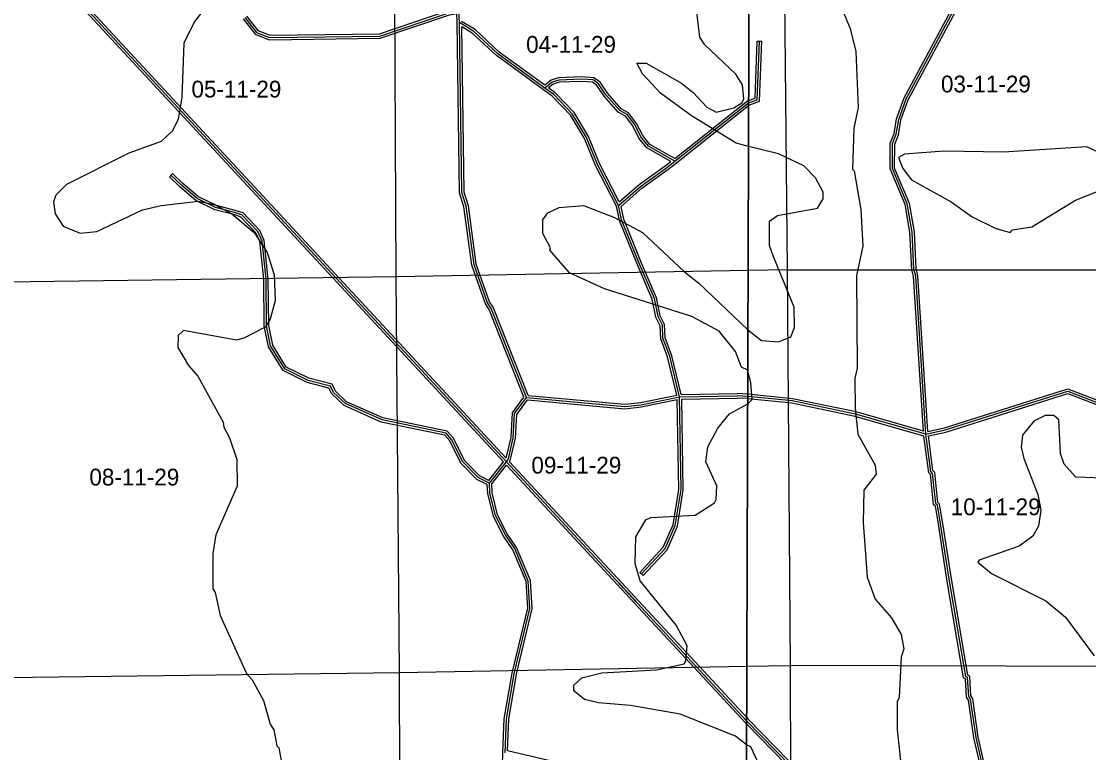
# Model space of a CAD drawing. Extents: x 457167 to 656239, y 1787309 to 1969297.
# Drawn here: x 527283 to 541585, y 1896458 to 1906256 of the extents above; entities that cross this region are included whole.
import ezdxf

# ---------------------------------------------------------------- set-up
doc = ezdxf.new("R2010")
doc.units = 0
for name, color, linetype in [('Level 1', 7, 'Continuous'), ('Level 2', 7, 'Continuous'), ('Level 31', 7, 'Continuous'), ('Level 32', 7, 'Continuous'), ('Level 34', 7, 'Continuous'), ('Level 63', 7, 'Continuous'), ('Level 7', 7, 'Continuous')]:
    doc.layers.add(name, color=color, linetype=linetype)

msp = doc.modelspace()

# ---------------------------------------------------------------- linework, layer by layer
at = {"layer": 'Level 1'}
for p, q in [((537491.16, 1908193.626), (537546.665, 1902924.331)), ((532306.15, 1902834.307), (532281.084, 1907962.091)), ((532306.15, 1902834.307), (527074.045, 1902759.436)), ((537021.377, 1902915.308), (532306.15, 1902834.307)), ((532349.253, 1897530.544), (532306.15, 1902834.307)), ((537546.665, 1902924.331), (537021.377, 1902915.308)), ((537546.665, 1902924.331), (542788.198, 1902925.546)), ((537546.665, 1902924.331), (537585.575, 1897625.288)), ((532349.253, 1897530.544), (537004.347, 1897614.771)), ((537004.347, 1897614.771), (537585.575, 1897625.288)), ((537585.575, 1897625.288), (537599.773, 1892290.637)), ((542838.747, 1897608.236), (537585.575, 1897625.288)), ((527079.285, 1897466.086), (532349.253, 1897530.544)), ((532368.304, 1892221.06), (532349.253, 1897530.544))]:
    msp.add_line(p, q, dxfattribs=at)
at = {"layer": 'Level 31'}
for p, q in [((533783.107, 1900354.301), (527053.695, 1907611.555)), ((533152.758, 1906238.376), (533145.019, 1906396.589)), ((536101.815, 1901225.282), (536875.394, 1901239.147)), ((533554.83, 1900067.776), (533783.107, 1900354.301))]:
    msp.add_line(p, q, dxfattribs=at)
for points in [[(539403.889, 1900723.442), (539267.811, 1902841.381), (539243.303, 1902933.097), (539219.447, 1903433.186), (539153.87, 1903808.675), (538955.089, 1904284.226), (538955.825, 1904617.687), (539006.131, 1904742.621), (539040.143, 1904942.521), (539140.832, 1905217.482), (539836.34, 1906516.053), (539828.149, 1906641.173), (539753.599, 1906791.23), (539205.078, 1907443.159), (538923.034, 1907918.973), (538840.41, 1908227.608), (538841.86, 1908786.165), (538892.32, 1908961.283), (538909.852, 1909277.964)], [(530277.025, 1906307.319), (530434.654, 1906106.777), (530609.585, 1906039.272), (532085.312, 1906058.661), (533011.74, 1906371.94), (533145.019, 1906396.589)], [(534051.109, 1901216.35), (533580.38, 1902410.301), (533530.714, 1902485.377), (533349.277, 1902994.72), (533243.784, 1903778.729), (533185.897, 1903962.199), (533152.758, 1906238.376)], [(534296.83, 1905361.84), (533668.266, 1905819.563), (533344.057, 1906120.646), (533152.758, 1906238.376)], [(537028.605, 1905164.967), (537143.114, 1905206.031), (537174.557, 1905989.588)], [(536041.144, 1904381.93), (535685.421, 1904582.364), (535583.468, 1904708.881), (535501.983, 1904873.151), (535400.059, 1905008.396), (535300.73, 1905061.813), (535117.03, 1905270.782), (535018.325, 1905417.656), (534945.063, 1905470.624), (534790.278, 1905480.222), (534486.015, 1905469.584), (534395.32, 1905440.791), (534296.83, 1905361.84)], [(535286.085, 1903787.642), (535004.943, 1904338.759), (534856.065, 1904697.802), (534665.41, 1905015.527), (534416.392, 1905274.898), (534296.83, 1905361.84)], [(536041.144, 1904381.93), (537028.537, 1905164.943), (537028.605, 1905164.967)], [(535286.085, 1903787.642), (535578.764, 1904044.877), (535929.91, 1904293.925), (536041.144, 1904381.93)], [(531425.795, 1901368.011), (531125.288, 1901444.664), (530812.653, 1901601.361), (530623.565, 1901907.101), (530568.842, 1902177.113), (530561.738, 1902801.518), (530507.831, 1903311.899), (530452.624, 1903437.908), (530236.884, 1903661.921), (530140.349, 1903694.613), (529886.24, 1903760.208), (529638.046, 1903881.423), (529427.885, 1904061.056), (529287.821, 1904193.54)], [(536101.815, 1901225.282), (535970.677, 1901767.541), (535879.58, 1902009.661), (535872.201, 1902184.963), (535814.083, 1902301.881), (535764.954, 1902543.866), (535566.791, 1903003.069), (535327.105, 1903595.867), (535286.085, 1903787.642)], [(533554.83, 1900067.776), (533405.01, 1900143.183), (533197.451, 1900352.605), (533048.698, 1900653.106), (532973.944, 1900736.995), (532115.786, 1900915.136), (531624.987, 1901133.516), (531467.163, 1901284.233), (531425.795, 1901368.011)], [(539403.889, 1900723.442), (539662.555, 1900781.175), (541306.314, 1901301.874), (542413.95, 1900873.718), (542755.475, 1900789.396), (543239.054, 1900788.284), (543805.714, 1900820.016), (544706.73, 1901026.027), (545795.278, 1901112.589)], [(533817.705, 1900433.462), (533874.142, 1900675.101), (533891.746, 1901000.142), (534051.109, 1901216.35)], [(534051.109, 1901216.35), (535367.915, 1901094.574), (535584.508, 1901118.96), (536101.815, 1901225.282)], [(535592.715, 1898851.237), (535910.82, 1899192.031), (536045.358, 1899499.966), (536122.275, 1899983.001), (536101.815, 1901225.282)], [(537015.964, 1901230.324), (537015.893, 1901230.331), (536875.394, 1901239.147)], [(539403.889, 1900723.442), (538462.692, 1900992.61), (537612.78, 1901169.87), (537015.964, 1901230.324)], [(540175.46, 1896228.182), (540076.653, 1896661.593), (540003.205, 1897170.562), (539978.215, 1897212.096), (539962.147, 1897462.334), (539937.08, 1897479.141), (539715.726, 1898780.231), (539600.733, 1899522.428), (539559.87, 1899772.746), (539534.829, 1899797.552), (539494.438, 1900198.053), (539469.399, 1900222.86), (539403.889, 1900723.442)], [(533783.107, 1900354.301), (533806.095, 1900383.681), (533817.705, 1900433.462)], [(533783.107, 1900354.301), (537001.932, 1896884.447), (537002, 1896884.377)], [(533766.432, 1896457.162), (533784.77, 1896907.296), (533887.255, 1897515.7), (534098.717, 1898389.935), (534075.124, 1898756.931), (533893.413, 1899190.997), (533769.065, 1899375.049), (533636.699, 1899634.038), (533562.656, 1899934.292), (533554.83, 1900067.776)], [(537002, 1896884.377), (538796.79, 1895046.313), (539676.085, 1894559.165)]]:
    msp.add_lwpolyline(points, dxfattribs=at)
at = {"layer": 'Level 32'}
for p, q in [((533743.569, 1900352.818), (527031.697, 1907591.156)), ((533779.608, 1900402.198), (527075.695, 1907631.953)), ((533122.769, 1906237.425), (533116.731, 1906360.846)), ((537144.581, 1905990.791), (537204.534, 1905988.385)), ((536059.785, 1904358.423), (537028.483, 1905126.611)), ((529267.205, 1904171.745), (529308.437, 1904215.335)), ((536125.324, 1901255.708), (536876.067, 1901269.164)), ((537016.06, 1901260.381), (536876.066, 1901269.164)), ((536132.306, 1901195.823), (536874.723, 1901209.13)), ((533779.608, 1900402.198), (533788.489, 1900440.276)), ((533546.552, 1900105.529), (533743.569, 1900352.818)), ((533585.453, 1900058.065), (533784.836, 1900308.325)), ((533822.494, 1900355.954), (537002.141, 1896928.335)), ((535570.785, 1898871.708), (535614.646, 1898830.766)), ((536069.689, 1895951.319), (533797.419, 1896480.746))]:
    msp.add_line(p, q, dxfattribs=at)
for points in [[(539371.222, 1900763.987), (539238.063, 1902836.5), (539213.49, 1902928.457), (539189.57, 1903429.877), (539124.895, 1903800.204), (538925.075, 1904278.24), (538925.838, 1904623.533), (538977.097, 1904750.835), (539011.028, 1904950.258), (539113.388, 1905229.784), (539805.843, 1906522.655), (539798.605, 1906633.211), (539728.33, 1906774.664), (539180.53, 1907425.735), (538895.121, 1907907.227), (538810.399, 1908223.7), (538811.87, 1908790.439), (538862.552, 1908966.329), (538878.72, 1909258.346)], [(539431.58, 1900760.361), (539297.56, 1902846.262), (539273.115, 1902937.736), (539249.324, 1903436.493), (539182.845, 1903817.146), (538985.103, 1904290.212), (538985.813, 1904611.841), (539035.165, 1904734.409), (539069.258, 1904934.782), (539168.276, 1905205.181), (539866.836, 1906509.452), (539857.693, 1906649.135), (539778.867, 1906807.796), (539229.625, 1907460.583), (538950.946, 1907930.72), (538870.42, 1908231.516), (538871.85, 1908781.89), (538922.087, 1908956.236), (538938.222, 1909247.672)], [(530300.612, 1906325.858), (530453.145, 1906131.798), (530614.982, 1906069.346), (532080.185, 1906088.596), (533004.169, 1906401.049), (533123.955, 1906423.201)], [(530253.438, 1906288.78), (530416.162, 1906081.756), (530604.188, 1906009.198), (532090.439, 1906028.725), (533019.313, 1906342.831), (533116.731, 1906360.846)], [(534017.111, 1901220.787), (533553.624, 1902396.372), (533503.679, 1902471.87), (533319.963, 1902987.61), (533214.395, 1903772.166), (533155.964, 1903957.366), (533122.769, 1906237.425)], [(534295.956, 1905399.588), (533687.371, 1905842.763), (533362.303, 1906144.645), (533181.951, 1906255.636)], [(534279.17, 1905337.588), (533649.161, 1905796.363), (533325.811, 1906096.648), (533183.552, 1906184.199)], [(534072.25, 1901244.522), (533607.136, 1902424.231), (533557.749, 1902498.885), (533378.59, 1903001.831), (533273.171, 1903785.291), (533215.83, 1903967.032), (533183.552, 1906184.198)], [(537028.483, 1905126.611), (537043.31, 1905138.37), (537172.279, 1905184.618), (537204.534, 1905988.385)], [(537028.708, 1905196.876), (537113.949, 1905227.443), (537144.581, 1905990.791)], [(536038.304, 1904417.965), (535705.166, 1904605.674), (535608.885, 1904725.151), (535527.62, 1904888.98), (535420.06, 1905031.704), (535319.695, 1905085.677), (535140.845, 1905289.13), (535040.24, 1905438.831), (534955.596, 1905500.029), (534790.684, 1905510.256), (534480.857, 1905499.423), (534380.915, 1905467.694), (534295.955, 1905399.588)], [(535987.484, 1904377.729), (535665.676, 1904559.054), (535558.05, 1904692.611), (535476.346, 1904857.322), (535380.058, 1904985.089), (535281.764, 1905037.949), (535093.214, 1905252.435), (534996.41, 1905396.48), (534934.53, 1905441.219), (534789.873, 1905450.189), (534491.173, 1905439.745), (534409.724, 1905413.886), (534346.245, 1905363.001)], [(535257.572, 1903777.516), (534977.683, 1904326.177), (534829.201, 1904684.265), (534641.427, 1904997.19), (534396.595, 1905252.2), (534279.186, 1905337.576)], [(535295.27, 1903835.656), (535032.204, 1904351.341), (534882.93, 1904711.339), (534689.395, 1905033.865), (534436.189, 1905297.596), (534346.245, 1905363.001)], [(536038.304, 1904417.965), (537013.764, 1905191.517), (537028.708, 1905196.876)], [(535295.27, 1903835.656), (535560.133, 1904068.444), (535911.912, 1904317.941), (535987.484, 1904377.729)], [(535319.101, 1903776.719), (535597.395, 1904021.311), (535947.906, 1904269.908), (536059.758, 1904358.401)], [(531405.006, 1901342.352), (531114.738, 1901416.394), (530791.61, 1901578.35), (530595.229, 1901895.884), (530538.876, 1902173.935), (530531.755, 1902799.769), (530478.485, 1903304.121), (530427.295, 1903420.958), (530220.342, 1903635.848), (530131.777, 1903665.841), (529875.803, 1903731.918), (529621.453, 1903856.14), (529407.818, 1904038.742), (529267.205, 1904171.745)], [(531446.585, 1901393.669), (531135.837, 1901472.933), (530833.696, 1901624.371), (530651.902, 1901918.319), (530598.809, 1902180.291), (530591.72, 1902803.268), (530537.178, 1903319.677), (530477.951, 1903454.858), (530253.425, 1903687.993), (530148.921, 1903723.385), (529896.679, 1903788.498), (529654.64, 1903906.706), (529447.951, 1904083.371), (529308.437, 1904215.335)], [(536065.356, 1901248.416), (535941.95, 1901758.7), (535849.808, 1902003.596), (535842.496, 1902177.324), (535785.465, 1902292.054), (535736.173, 1902534.842), (535539.109, 1902991.501), (535298.315, 1903587.041), (535257.572, 1903777.516)], [(536125.324, 1901255.708), (535999.404, 1901776.382), (535909.352, 1902015.726), (535901.907, 1902192.602), (535842.7, 1902311.71), (535793.734, 1902552.89), (535594.475, 1903014.637), (535355.897, 1903604.693), (535319.101, 1903776.718)], [(533525.895, 1900048.754), (533387.149, 1900118.586), (533172.721, 1900334.939), (533023.607, 1900636.17), (532958.14, 1900709.635), (532106.534, 1900886.416), (531608.034, 1901108.222), (531442.61, 1901266.197), (531405.006, 1901342.352)], [(533546.552, 1900105.529), (533422.872, 1900167.78), (533222.182, 1900370.271), (533073.789, 1900670.044), (532989.746, 1900764.355), (532125.038, 1900943.856), (531641.94, 1901158.809), (531491.715, 1901302.269), (531446.585, 1901393.669)], [(539371.221, 1900763.987), (538469.889, 1901021.755), (537617.367, 1901199.56), (537018.345, 1901260.237), (537016.06, 1901260.381)], [(539431.58, 1900760.361), (539654.742, 1900810.171), (541307.3, 1901333.656), (542422.99, 1900902.388), (542759.157, 1900819.389), (543238.249, 1900818.286), (543801.501, 1900849.827), (544702.173, 1901055.761), (545742.53, 1901138.489)], [(539437.195, 1900700.136), (539670.366, 1900752.179), (541305.327, 1901270.091), (542404.911, 1900845.048), (542751.791, 1900759.404), (543239.858, 1900758.281), (543809.926, 1900790.204), (544711.285, 1900996.294), (545797.655, 1901082.682)], [(533788.491, 1900440.286), (533844.329, 1900679.356), (533862.275, 1901010.722), (534017.111, 1901220.787)], [(533846.92, 1900426.639), (533903.956, 1900670.845), (533921.218, 1900989.562), (534065.211, 1901184.916)], [(534065.21, 1901184.916), (535368.216, 1901064.417), (535589.216, 1901089.301), (536072.416, 1901188.611)], [(534072.25, 1901244.523), (535367.615, 1901124.731), (535579.8, 1901148.62), (536065.356, 1901248.416)], [(535570.785, 1898871.708), (535885.385, 1899208.747), (536016.334, 1899508.466), (536092.235, 1899985.13), (536072.416, 1901188.611)], [(535614.646, 1898830.766), (535936.255, 1899175.313), (536074.383, 1899491.466), (536152.315, 1899980.874), (536132.306, 1901195.823)], [(537015.866, 1901200.18), (537013.44, 1901200.426), (536874.724, 1901209.13)], [(539376.7, 1900700.014), (538455.496, 1900963.465), (537608.193, 1901140.18), (537015.866, 1901200.18)], [(540146.665, 1896219.522), (540047.133, 1896656.107), (539974.377, 1897160.285), (539948.744, 1897202.886), (539933.155, 1897445.652), (539909.667, 1897461.401), (539686.113, 1898775.417), (539571.105, 1899517.715), (539531.83, 1899758.292), (539506.061, 1899783.822), (539465.67, 1900184.323), (539440.985, 1900208.779), (539376.7, 1900700.015)], [(540204.256, 1896236.841), (540106.172, 1896667.079), (540032.033, 1897180.841), (540007.686, 1897221.306), (539991.138, 1897479.016), (539964.494, 1897496.881), (539745.34, 1898785.043), (539630.361, 1899527.142), (539587.908, 1899787.198), (539563.597, 1899811.282), (539523.205, 1900211.783), (539497.812, 1900236.941), (539437.195, 1900700.136)], [(533822.494, 1900355.954), (533833.806, 1900370.412), (533846.922, 1900426.648)], [(533784.836, 1900308.325), (536980.198, 1896863.762), (537001.862, 1896841.576)], [(533736.444, 1896458.001), (533754.871, 1896910.411), (533857.846, 1897521.726), (534068.485, 1898392.559), (534045.508, 1898749.987), (533866.889, 1899176.667), (533743.183, 1899359.768), (533608.404, 1899623.481), (533532.868, 1899929.785), (533525.895, 1900048.754)], [(533797.42, 1896480.746), (533814.669, 1896904.181), (533916.662, 1897509.674), (534128.949, 1898387.311), (534104.74, 1898763.876), (533919.937, 1899205.327), (533794.947, 1899390.33), (533664.995, 1899644.596), (533592.444, 1899938.799), (533585.453, 1900058.065)], [(537001.862, 1896841.576), (538778.4, 1895022.204), (539661.545, 1894532.922)], [(537002.141, 1896928.335), (537023.665, 1896905.131), (538815.179, 1895070.421), (539665.508, 1894599.321)], [(534496.094, 1894042.885), (533875.793, 1895135.635), (533766.995, 1895457.841), (533717.258, 1895771.626), (533736.444, 1896458.001)]]:
    msp.add_lwpolyline(points, dxfattribs=at)
at = {"layer": 'Level 63'}
for points in [[(497176.54, 1878534.741), (536942.563, 1878385.707), (537088.612, 1923840.983), (497371.386, 1923990.389), (497176.54, 1878534.741)], [(536942.563, 1878385.707), (576708.29, 1878279.4), (576805.546, 1923734.416), (537088.612, 1923840.983), (536942.563, 1878385.707)]]:
    msp.add_lwpolyline(points, dxfattribs=at)
at = {"layer": 'Level 7'}
for points in [[(538142.63, 1906753.116), (538390.794, 1906160.446), (538464.84, 1905851.74), (538495.773, 1905101.372), (538436.536, 1904826.465), (538418.105, 1904276.331), (538443.045, 1904251.231), (538533.075, 1903734.081), (538556.524, 1903242.169), (538471.879, 1902850.618), (538484.569, 1901608.469), (538450.8, 1901475.186), (538457.867, 1901075.006), (538490.103, 1900724.788), (538722.174, 1900307.211), (538738.456, 1900190.439), (538571.046, 1899974.251), (538561.303, 1899540.791), (538617.306, 1898806.995), (538724.763, 1898514.869), (538940.69, 1898264.086), (539073.357, 1898038.582), (539106.08, 1897846.748), (539072.411, 1897738.475), (539045.64, 1897196.671), (539020.46, 1897138.42), (539019.256, 1896763.281), (539067.835, 1896312.951)], [(529755.252, 1906446.602), (529604.573, 1906255.356), (529461.915, 1905964.007), (529434.586, 1905238.84), (529383.62, 1904947.232), (529308.101, 1904789.068), (529157.591, 1904647.842), (528723.575, 1904490.853), (527888.606, 1904068.382), (527746.436, 1903927.117), (527712.797, 1903835.525), (527737.28, 1903677.031), (527845.135, 1903509.979), (528069.92, 1903417.56), (528295.065, 1903441.843), (528904.561, 1903731.657), (529154.845, 1903789.192), (529655.194, 1903845.95), (529880.109, 1903795.211), (530104.825, 1903677.781), (530404.125, 1903426.71), (530578.333, 1903159.396), (530669.09, 1902858.99), (530684.645, 1902517.161), (530617.139, 1902267.275), (530550.129, 1902159.131), (530266.206, 1902009.984), (530166.105, 1901985.272), (529457.909, 1902112.606), (529382.649, 1902046.144), (529382.161, 1901887.751), (529523.098, 1901645.576), (529647.683, 1901503.435), (529987.51, 1900885.464), (529995.62, 1900818.743), (530070.185, 1900676.791), (530169.281, 1900384.695), (530176.467, 1900026.196), (529890.943, 1899376.877), (529848.486, 1899126.921), (529846.944, 1898651.74), (529880.125, 1898601.629), (529945.842, 1898292.952), (530301.821, 1897516.529), (530376.585, 1897432.938), (530525.761, 1897157.343), (530616.409, 1896840.266), (530666.2, 1896765.076), (530707.195, 1896548.201), (530732.106, 1896523.131), (530781.281, 1896256.205)], [(537026.729, 1904580.938), (536860.32, 1904623.13), (536261.282, 1904991.851), (535845.439, 1905293.273), (535604.51, 1905552.486), (535529.936, 1905694.458), (535654.979, 1905694.04), (536129.302, 1905425.77), (536287.267, 1905300.199), (536470.084, 1905107.876), (536594.897, 1905040.796), (536828.511, 1905098.401), (536937.072, 1905164.724), (536962.252, 1905214.686), (536946.198, 1905406.45), (536854.955, 1905548.461), (536439.38, 1905941.616), (536373.017, 1906041.877), (536324.3, 1906450.526)], [(537018.829, 1902121.898), (537019.043, 1902121.693), (537201.989, 1901979.391), (537427.003, 1901961.964), (537593.925, 1902028.138), (537644.364, 1902153.011), (537636.91, 1902428.148), (537355.663, 1903112.641), (537306.1, 1903254.523), (537307.145, 1903579.641), (537415.745, 1903654.314), (537949.604, 1903752.643), (538025.024, 1903877.427), (538025.312, 1903969.129), (537925.897, 1904161.192), (537768.031, 1904320.075), (537426.732, 1904479.574), (537026.913, 1904580.891), (537026.729, 1904580.938)], [(537017.086, 1901579.928), (536934.049, 1901621.78), (536851.374, 1901830.444), (536635.505, 1902106.237), (536269.335, 1902299.147), (535095.087, 1902669.741), (534628.935, 1902887.951), (534363.155, 1903188.944), (534371.585, 1903222.255), (534272.17, 1903414.318), (534272.766, 1903597.723), (534339.746, 1903689.196), (534490.028, 1903763.73), (534815.244, 1903787.694), (535231.534, 1903627.966), (535606.015, 1903426.716), (536171.224, 1902899.691), (536362.47, 1902749.019), (537018.829, 1902121.898)], [(537015.64, 1901129.555), (537015.849, 1901129.669), (537074.399, 1901187.831), (537058.445, 1901412.976), (537017.281, 1901579.83), (537017.086, 1901579.928)], [(537000.963, 1896561.512), (536851.517, 1896678.541), (536110.539, 1896972.7), (535443.985, 1897091.534), (535018.966, 1897126.259), (534827.361, 1897168.558), (534686.007, 1897285.729), (534686.236, 1897360.751), (534794.936, 1897460.434), (535061.92, 1897526.269), (535795.653, 1897565.6), (536162.709, 1897647.786), (536187.849, 1897689.367), (536205.175, 1897889.412), (536055.999, 1898164.967), (535574.39, 1898758.415), (535508.445, 1898992.03), (535517.929, 1899350.458), (535652.028, 1899575.116), (535718.819, 1899608.266), (536310.83, 1899639.715), (536569.771, 1899805.592), (536594.911, 1899847.214), (536603.839, 1900030.578), (536454.83, 1900356.184), (536480.488, 1900556.159), (536614.656, 1900805.826), (536773.666, 1900997.043), (537015.64, 1901129.555)], [(541906.097, 1900130.258), (541414.317, 1900148.532), (541256.481, 1900324.084), (541206.919, 1900465.966), (541183.351, 1900916.197), (541116.859, 1900974.778), (541000.146, 1900975.136), (540849.835, 1900900.602), (540699.195, 1900709.356), (540681.997, 1900551.032), (540714.85, 1900400.839), (540905.051, 1899916.71), (540946.045, 1899708.176), (540912.018, 1899491.56), (540836.569, 1899358.406), (540652.738, 1899225.611), (540118.6, 1899035.579), (540101.86, 1899010.628), (540284.766, 1898859.987), (541008.856, 1898490.867), (541274.925, 1898273.276), (541656.73, 1897755.178)], [(536993.032, 1894093.554), (536993.281, 1894093.782), (537135.78, 1894335.08), (537136.955, 1894701.879), (537103.773, 1894752.029), (537112.989, 1895027.096), (537138.258, 1895110.358), (537305.479, 1895259.894), (537422.738, 1895434.56), (537456.875, 1895684.556), (537059.474, 1896536.141), (537001.182, 1896561.341), (537000.963, 1896561.512)]]:
    msp.add_lwpolyline(points, dxfattribs=at)
msp.add_lwpolyline([(540566.289, 1903460.78), (540824.853, 1903501.644), (541409.539, 1903858.24), (541801.864, 1904015.358), (541935.535, 1904114.972), (541935.963, 1904248.356), (541720.035, 1904499.129), (541561.87, 1904574.679), (540444.58, 1904503.243), (539644.325, 1904514.133), (539119.005, 1904474.156), (539035.514, 1904432.733), (539093.378, 1904282.481), (539209.592, 1904132.068), (539742.207, 1903838.598), (540024.985, 1903637.607), (540332.944, 1903486.537), (540532.849, 1903427.558), (540566.289, 1903460.78)], close=True, dxfattribs=at)

# ---------------------------------------------------------------- texts
at = {"layer": 'Level 2'}
for s, p in [('04-11-29', (534046.825, 1905834.626)), ('05-11-29', (529562.78, 1905235.263)), ('03-11-29', (539605.816, 1905303.481)), ('09-11-29', (534117.541, 1900196.808)), ('08-11-29', (528194.875, 1900037.036)), ('10-11-29', (539736.807, 1899639.049))]:
    msp.add_text(s, height=225, dxfattribs=at).set_placement(p)
at = {"layer": 'Level 34'}
msp.add_text('OLD RAILROAD BED', height=25, rotation=312.8499778, dxfattribs=at).set_placement((535283.11, 1898718.938))

doc.saveas('drawing.dxf')
